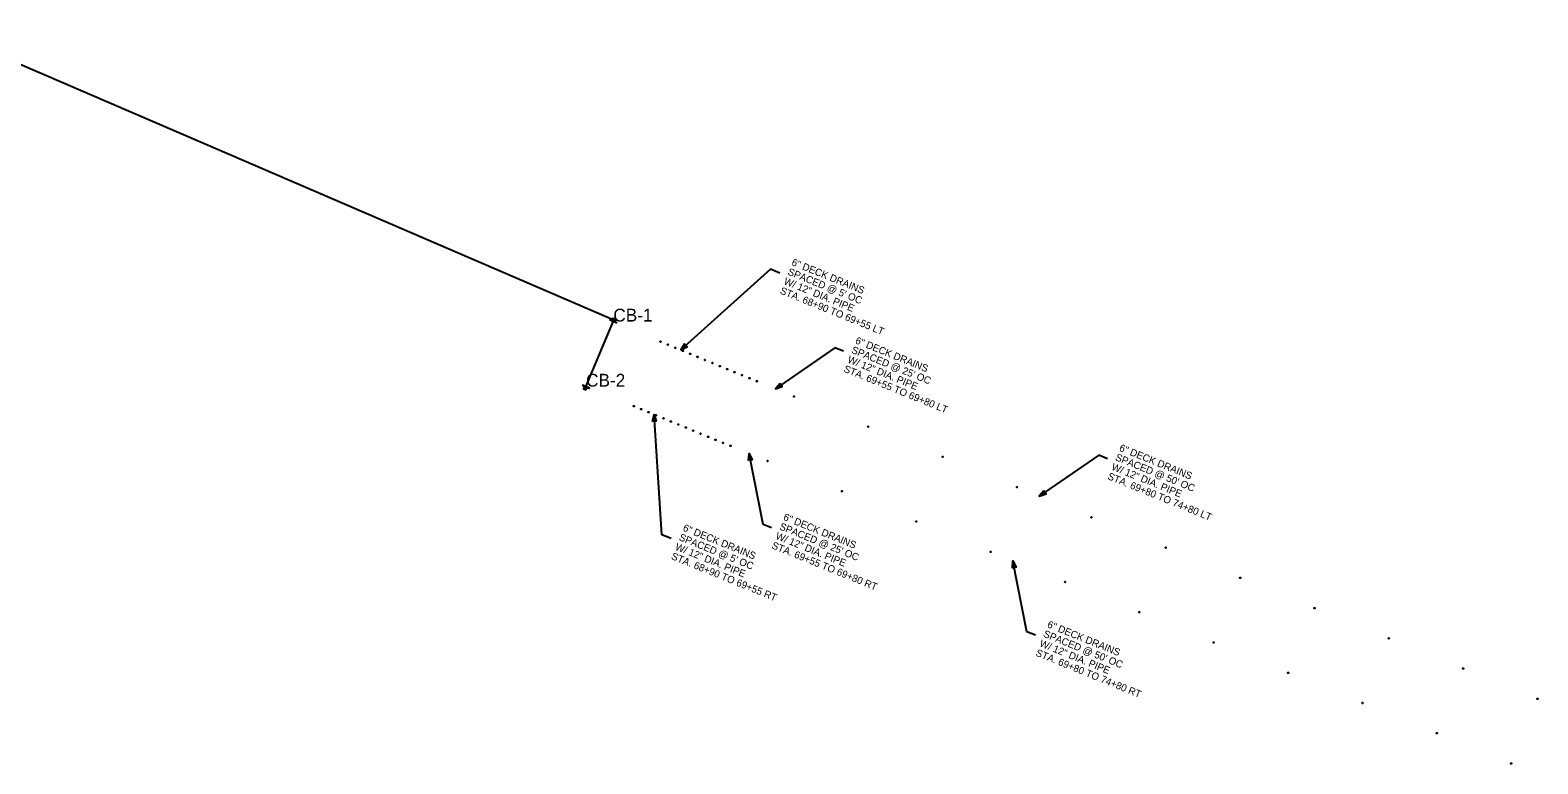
# Model space of a CAD drawing. Extents: x 2165744 to 2171481, y 206867 to 209489.
# Drawn here: x 2166683 to 2167622, y 208496 to 208954 of the extents above; entities that cross this region are included whole.
import ezdxf

# ---------------------------------------------------------------- set-up
doc = ezdxf.new("R2010")
doc.units = 0
for name, color, linetype in [('RD_PD_DR_Inlet', 7, 'Continuous'), ('RD_PD_DR_Inlet_TX', 7, 'Continuous'), ('RD_PD_DR_Pipe', 7, 'Continuous'), ('RD_TX_Drainage', 7, 'Continuous')]:
    doc.layers.add(name, color=color, linetype=linetype)

msp = doc.modelspace()

# ---------------------------------------------------------------- linework, layer by layer
at = {"layer": 'RD_PD_DR_Inlet'}
for p, q in [((2167044.2, 208772.8), (2167044.2, 208772.8)), ((2167046.02, 208773.13), (2167046.02, 208773.13)), ((2167046.25, 208771.95), (2167046.54, 208772.65)), ((2167046.25, 208771.95), (2167046.25, 208771.95)), ((2167046.25, 208771.95), (2167046.25, 208771.95)), ((2167046.31, 208772.1), (2167046.31, 208772.1)), ((2167046.38, 208772.25), (2167046.38, 208772.25)), ((2167046.63, 208772.87), (2167046.63, 208772.87)), ((2167046.89, 208773.48), (2167046.89, 208773.48)), ((2167046.89, 208773.48), (2167046.89, 208773.48)), ((2167047.25, 208772.61), (2167047.25, 208772.61)), ((2167027.22, 208732.21), (2167027.22, 208732.21)), ((2167028.27, 208730.69), (2167028.27, 208730.69)), ((2167029.27, 208731.36), (2167028.97, 208730.65)), ((2167029.14, 208731.05), (2167029.14, 208731.05)), ((2167029.2, 208731.2), (2167029.2, 208731.2)), ((2167029.27, 208731.36), (2167029.27, 208731.36)), ((2167029.27, 208731.36), (2167029.27, 208731.36)), ((2167028.62, 208729.82), (2167028.62, 208729.82)), ((2167028.62, 208729.82), (2167028.62, 208729.82)), ((2167028.88, 208730.43), (2167028.88, 208730.43)), ((2167029.5, 208730.18), (2167029.5, 208730.18))]:
    msp.add_line(p, q, dxfattribs=at)
for points in [[(2167047.78, 208773.3), (2167047.13, 208771.76), (2167048.36, 208771.24), (2167048.3, 208771.09), (2167044.2, 208772.8), (2167044.26, 208772.96), (2167045.49, 208772.44), (2167046.14, 208773.98)], [(2167046.99, 208772), (2167045.76, 208772.51), (2167046.28, 208773.74), (2167047.51, 208773.23)], [(2167029.38, 208729.32), (2167030.02, 208730.86), (2167031.25, 208730.34), (2167031.32, 208730.5), (2167027.22, 208732.21), (2167027.15, 208732.06), (2167028.38, 208731.55), (2167027.74, 208730.01)], [(2167029.75, 208730.79), (2167028.52, 208731.31), (2167028.01, 208730.08), (2167029.24, 208729.56)]]:
    msp.add_lwpolyline(points, close=True, dxfattribs=at)
for centre in [(2167075.64, 208759.43), (2167080.25, 208757.52), (2167084.86, 208755.6), (2167089.47, 208753.69), (2167094.08, 208751.79), (2167098.69, 208749.88), (2167103.31, 208747.98), (2167107.92, 208746.08), (2167112.54, 208744.18), (2167117.15, 208742.28), (2167121.77, 208740.38), (2167126.39, 208738.49), (2167131.01, 208736.6), (2167135.62, 208734.71), (2167158.74, 208725.28), (2167058.95, 208719.25), (2167063.58, 208717.33), (2167068.21, 208715.42), (2167072.84, 208713.5), (2167077.46, 208711.59), (2167082.09, 208709.67), (2167086.73, 208707.76), (2167091.36, 208705.85), (2167095.99, 208703.95), (2167205.05, 208706.43), (2167100.62, 208702.04), (2167105.26, 208700.14), (2167109.89, 208698.24), (2167114.52, 208696.34), (2167119.16, 208694.45), (2167142.34, 208684.99), (2167251.36, 208687.57), (2167188.65, 208666.14), (2167297.67, 208668.72), (2167234.96, 208647.28), (2167343.98, 208649.86), (2167281.27, 208628.43), (2167390.29, 208631.01), (2167327.57, 208609.57), (2167436.6, 208612.15), (2167373.88, 208590.72), (2167482.9, 208593.3), (2167420.19, 208571.86), (2167529.21, 208574.44), (2167466.5, 208553.01), (2167575.52, 208555.59), (2167512.81, 208534.15), (2167621.83, 208536.73), (2167559.12, 208515.3), (2167605.43, 208496.44)]:
    msp.add_circle(centre, 0.25, dxfattribs=at)
at = {"layer": 'RD_PD_DR_Pipe'}
for p, q in [((2167046.63, 208772.86), (2166626.69, 208953.62)), ((2167029.2, 208731.2), (2167046.63, 208772.86))]:
    msp.add_line(p, q, dxfattribs=at)
at = {"layer": 'RD_TX_Drainage'}
for points in [[(2167149.91, 208802.16), (2167144.07, 208804.54), (2167088.2, 208754.22)], [(2167189.61, 208753.39), (2167184.3, 208755.55), (2167147.18, 208730)], [(2167082.22, 208636.62), (2167076.38, 208639), (2167071.57, 208714.03)], [(2167144.77, 208643.34), (2167139.46, 208645.5), (2167130.76, 208689.72)], [(2167354, 208686.45), (2167348.69, 208688.61), (2167311.56, 208663.06)], [(2167309.17, 208576.39), (2167303.87, 208578.55), (2167295.16, 208622.77)]]:
    msp.add_lwpolyline(points, dxfattribs=at)
for points in [[(2167090.65, 208758), (2167088.2, 208754.22), (2167092.21, 208756.26)], [(2167150.1, 208733.42), (2167147.18, 208730), (2167151.42, 208731.5)], [(2167070.68, 208709.62), (2167071.57, 208714.03), (2167073.01, 208709.76)], [(2167130.45, 208685.23), (2167130.76, 208689.72), (2167132.74, 208685.68)], [(2167314.48, 208666.48), (2167311.56, 208663.06), (2167315.8, 208664.57)], [(2167294.86, 208618.28), (2167295.16, 208622.77), (2167297.14, 208618.73)]]:
    msp.add_lwpolyline(points, close=True, dxfattribs=at)

# ---------------------------------------------------------------- texts
at = {"layer": 'RD_PD_DR_Inlet_TX'}
for s, p in [('CB-1', (2167046.25, 208771.95)), ('CB-2', (2167029.27, 208731.36))]:
    msp.add_text(s, height=8, dxfattribs=at).set_placement(p)
at = {"layer": 'RD_TX_Drainage'}
for s, p in [('6" DECK DRAINS', (2167156.84, 208807.23)), ('W/ 12" DIA. PIPE ', (2167152.03, 208795.42)), ("SPACED @ 5' OC ", (2167154.43, 208801.33)), ('STA. 68+90 TO 69+55 LT', (2167149.62, 208789.52)), ('6" DECK DRAINS', (2167196.54, 208758.46)), ('W/ 12" DIA. PIPE ', (2167191.73, 208746.65)), ("SPACED @ 25' OC ", (2167194.13, 208752.56)), ('STA. 69+55 TO 69+80 LT', (2167189.32, 208740.75)), ('6" DECK DRAINS', (2167360.92, 208691.52)), ('W/ 12" DIA. PIPE ', (2167356.11, 208679.72)), ("SPACED @ 50' OC ", (2167358.52, 208685.62)), ('STA. 69+80 TO 74+80 LT', (2167353.71, 208673.81)), ("SPACED @ 25' OC ", (2167149.29, 208642.51)), ('6" DECK DRAINS', (2167151.7, 208648.41)), ("SPACED @ 5' OC ", (2167086.74, 208635.79)), ('6" DECK DRAINS', (2167089.15, 208641.69)), ('W/ 12" DIA. PIPE ', (2167146.89, 208636.6)), ('STA. 68+90 TO 69+55 RT', (2167081.93, 208623.98)), ('W/ 12" DIA. PIPE ', (2167084.34, 208629.88)), ('STA. 69+55 TO 69+80 RT', (2167144.48, 208630.7)), ('6" DECK DRAINS', (2167316.1, 208581.47)), ('W/ 12" DIA. PIPE ', (2167311.29, 208569.66)), ("SPACED @ 50' OC ", (2167313.7, 208575.56)), ('STA. 69+80 TO 74+80 RT', (2167308.89, 208563.75))]:
    msp.add_text(s, height=4.5, rotation=337.83882, dxfattribs=at).set_placement(p)

doc.saveas('drawing.dxf')
